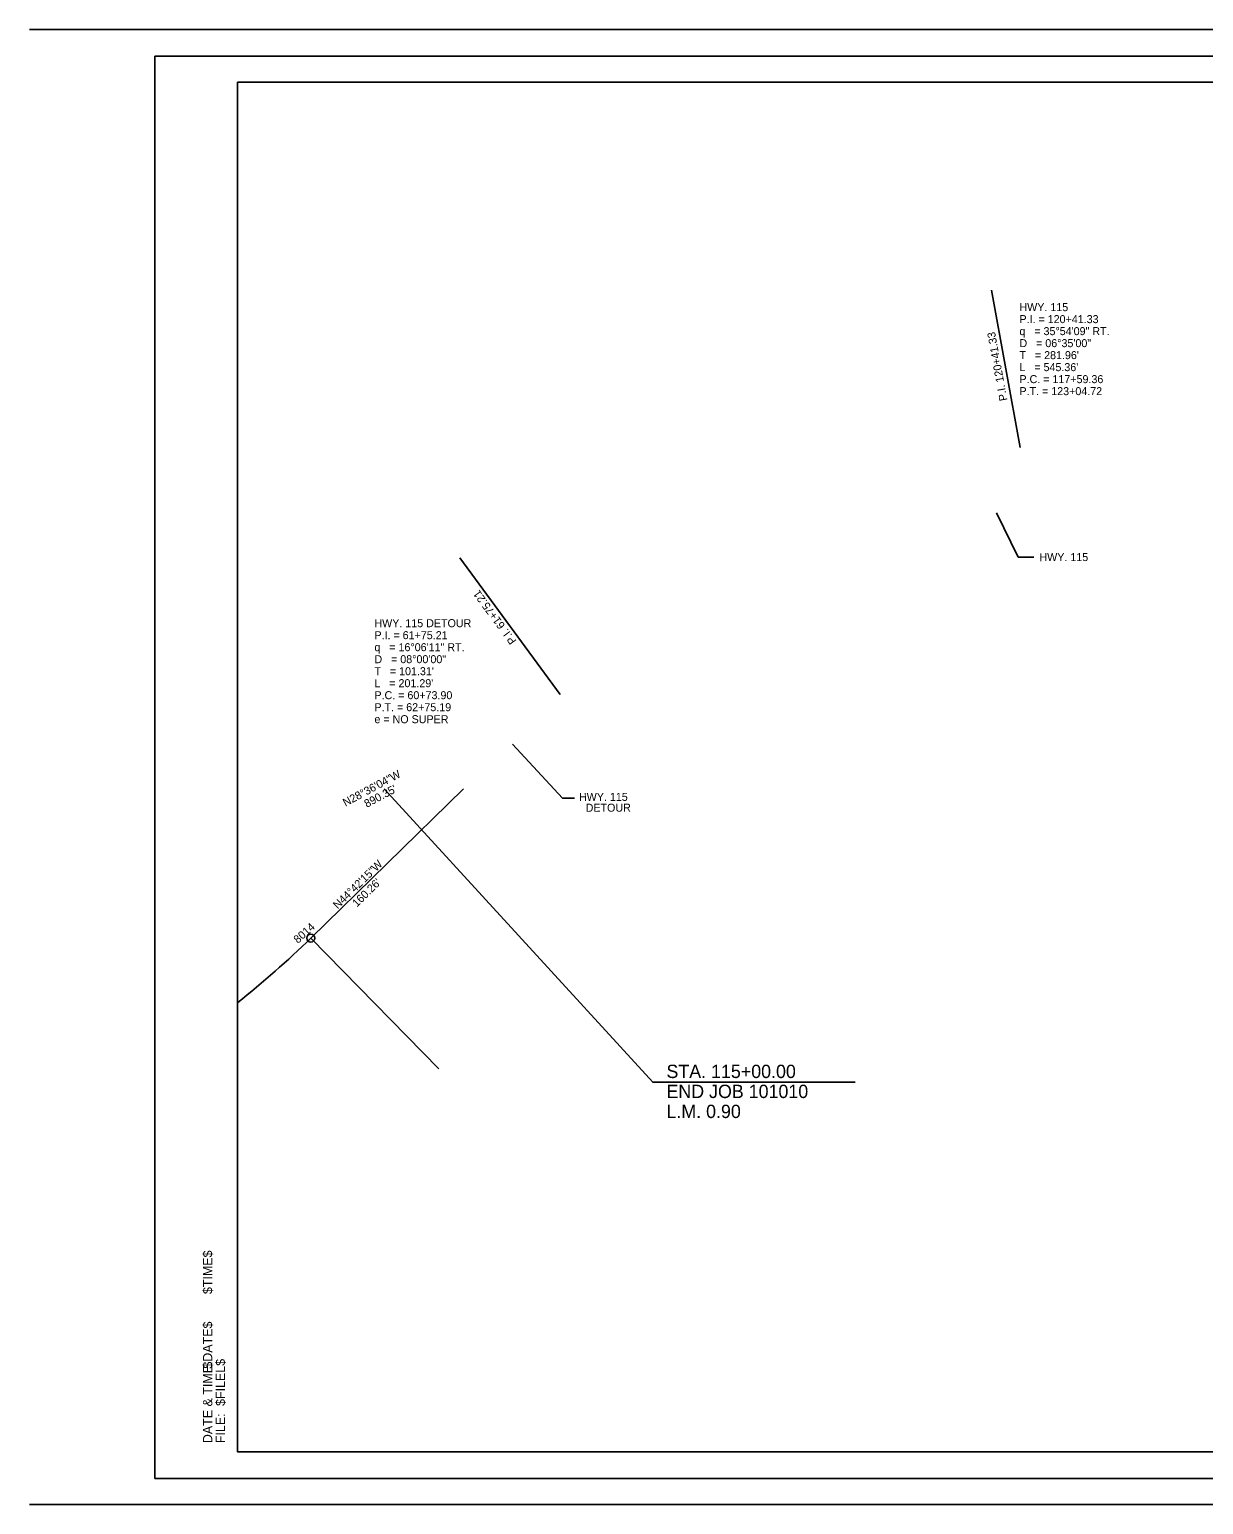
# Model space of a CAD drawing. Extents: x 3698 to 9589, y 10000 to 11106.
# Drawn here: x 7828 to 8709, y 10000 to 11106 of the extents above; entities that cross this region are included whole.
import ezdxf

# ---------------------------------------------------------------- set-up
doc = ezdxf.new("R2010")
doc.units = 0
for name, color, linetype in [('DATE', 7, 'Continuous'), ('GREEN_TXT', 7, 'Continuous'), ('R_Clearzone', 7, 'Continuous'), ('R_Culvert', 7, 'Continuous'), ('R_Detour', 7, 'Continuous'), ('R_Detour Annot', 7, 'Continuous'), ('R_Ditch', 7, 'Continuous'), ('R_Proposed Const Limits', 7, 'Continuous'), ('R_Sub Surface', 7, 'Continuous'), ('T_Drafting', 7, 'Continuous')]:
    doc.layers.add(name, color=color, linetype=linetype)

msp = doc.modelspace()

# ---------------------------------------------------------------- linework, layer by layer
at = {"layer": 'DATE'}
msp.add_lwpolyline([(7984.2, 11066.7), (7984.2, 10039.4), (9565.1, 10039.4), (9565.1, 11002.7), (9349.6, 11002.7), (9349.6, 11001.3), (9333.5, 11001.3), (9333.5, 11017.3), (9153.8, 11017.3), (9153.8, 11066.7)], close=True, dxfattribs=at)
msp.add_lwpolyline([(7984.2, 11066.7), (7984.2, 10039.4), (9565.1, 10039.4), (9565.1, 11002.7), (9349.6, 11002.7), (9349.6, 11001.3), (9333.5, 11001.3), (9333.5, 11017.3), (9153.8, 11017.3), (9153.8, 11066.7)], close=True, dxfattribs=at)
at = {"layer": 'GREEN_TXT'}
for p, q in [((9588.1, 11106.1), (7828.1, 11106.1)), ((7984.2, 11066.7), (9565.1, 11066.7)), ((7984.2, 10039.4), (7984.2, 11066.7)), ((9565.1, 10039.4), (7984.2, 10039.4)), ((7828.1, 10000), (9588.1, 10000))]:
    msp.add_line(p, q, dxfattribs=at)
at = {"layer": 'R_Clearzone'}
msp.add_lwpolyline([(7922.2, 11086.2), (9588.9, 11086.2), (9588.9, 10019.5), (7922.2, 10019.5)], close=True, dxfattribs=at)
at = {"layer": 'R_Culvert'}
for points in [[(8571, 10792.6), (8549.5, 10910.7)], [(8581.4, 10710.5), (8569.6, 10710.5), (8553.2, 10743.7)]]:
    msp.add_lwpolyline(points, dxfattribs=at)
msp.add_circle((8039.1, 10424.7), 3, dxfattribs=at)
at = {"layer": 'R_Detour'}
msp.add_lwpolyline([(8447.4, 10316.6), (8295.5, 10316.6), (8094, 10536.6)], dxfattribs=at)
at = {"layer": 'R_Detour Annot'}
for points in [[(8226.2, 10607.5), (8150.9, 10710)], [(8236.9, 10529.7), (8227.9, 10529.7), (8190.4, 10570.2)], [(8039.1, 10424.7), (8135, 10326.6)]]:
    msp.add_lwpolyline(points, dxfattribs=at)
at = {"layer": 'R_Ditch'}
msp.add_line((8039.1, 10424.7), (8153.7, 10536.7), dxfattribs=at)
msp.add_arc((7538.6, 10937), 716.2, 308.4819, 314.3359, dxfattribs=at)

# ---------------------------------------------------------------- texts
for s, height, p in [('$TIME$', 6.98, (7965.2, 10157.8)), ('$DATE$', 6.98, (7965.2, 10101.9)), ('DATE & TIME:', 6.984, (7965.2, 10046)), ('$FILEL$', 6.98, (7974.8, 10073.9)), ('FILE: ', 6.98, (7974.8, 10046))]:
    msp.add_text(s, height=height, rotation=90).set_placement(p)
at = {"layer": 'R_Culvert'}
for s, p in [('HWY. 115', (8570.5, 10894.9)), ('P.I. = 120+41.33', (8570.5, 10885.9)), ('q   = 35%%d54\'09" RT.', (8570.5, 10876.9)), ('D   = 06%%d35\'00"', (8570.5, 10867.9)), ("T   = 281.96'", (8570.5, 10858.9)), ("L   = 545.36'", (8570.5, 10849.9)), ('P.C. = 117+59.36', (8570.5, 10840.9)), ('P.T. = 123+04.72', (8570.5, 10831.9))]:
    msp.add_text(s, height=6, dxfattribs=at).set_placement(p)
for s, rotation, p in [('P.I. 120+41.33', 100.2814, (8561.5, 10828.1)), ('HWY. 115', 0.1002, (8585.5, 10707.4)), ('N28%%d36\'04"W', 28.333, (8065.1, 10523.2)), ('HWY. 115', 0.1002, (8240.2, 10527.6)), ('DETOUR', 0.1002, (8245.2, 10519.5))]:
    msp.add_text(s, height=6, rotation=rotation, dxfattribs=at).set_placement(p)
at = {"layer": 'R_Detour'}
for s, p in [('STA. 115+00.00', (8305.8, 10319.8)), ('END JOB 101010', (8305.8, 10304.8)), ('L.M. 0.90', (8305.8, 10289.8))]:
    msp.add_text(s, height=10, dxfattribs=at).set_placement(p)
at = {"layer": 'R_Detour Annot'}
msp.add_text('P.I. 61+75.21', height=6, rotation=126.2843, dxfattribs=at).set_placement((8193.6, 10647.7))
for s, p in [('HWY. 115 DETOUR', (8086.8, 10657.9)), ('P.I. = 61+75.21', (8086.8, 10648.9)), ('q   = 16%%d06\'11" RT.', (8086.8, 10639.9)), ('D   = 08%%d00\'00"', (8086.8, 10630.9)), ("T   = 101.31'", (8086.8, 10621.9)), ("L   = 201.29'", (8086.8, 10612.9)), ('P.C. = 60+73.90', (8086.8, 10603.9)), ('P.T. = 62+75.19', (8086.8, 10594.9)), ('e = NO SUPER', (8086.8, 10585.9))]:
    msp.add_text(s, height=6, dxfattribs=at).set_placement(p)
at = {"layer": 'R_Proposed Const Limits'}
for s, p in [('N44%%d42\'15"W', (8059.3, 10446.2)), ("160.26'", (8073.6, 10447.6))]:
    msp.add_text(s, height=6, rotation=44.3359, dxfattribs=at).set_placement(p)
at = {"layer": 'R_Sub Surface'}
msp.add_text('8014', height=6, rotation=41.647, dxfattribs=at).set_placement((8029.4, 10420.4))
at = {"layer": 'T_Drafting'}
msp.add_text("890.35'", height=6, rotation=28.1453, dxfattribs=at).set_placement((8081.1, 10522.4))

doc.saveas('drawing.dxf')
